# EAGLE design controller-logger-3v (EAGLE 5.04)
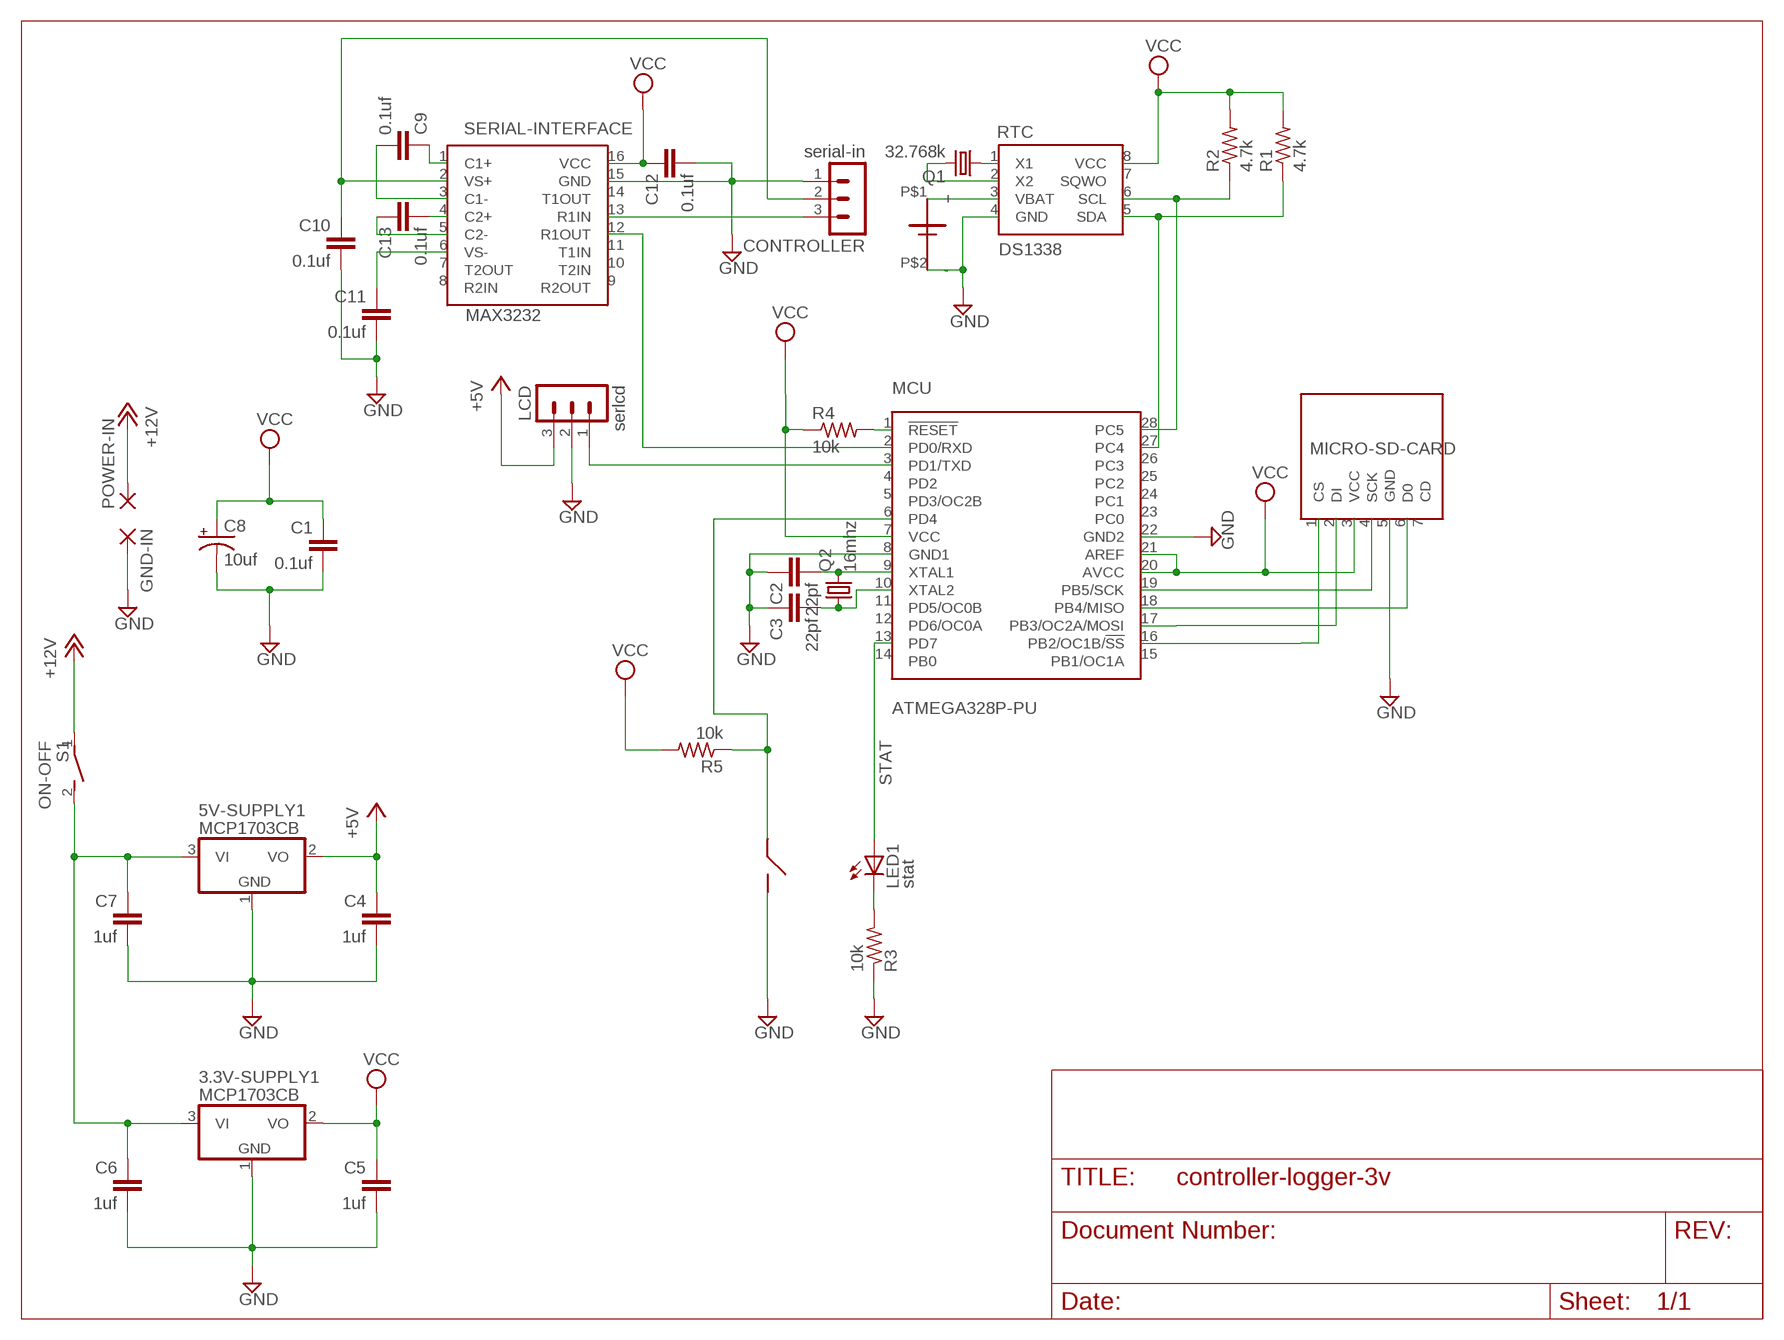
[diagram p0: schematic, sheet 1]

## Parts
3.3V-SUPPLY1  MCP1703CB  [SOT23]
5V-SUPPLY1  MCP1703CB  [SOT23]
C1  0.1uf  C2.5/2  [C2.5-2]
C2  22pf  C2.5/2  [C2.5-2]
C3  22pf  C2.5/2  [C2.5-2]
C4  1uf  C2.5/2  [C2.5-2]
C5  1uf  C2.5/2  [C2.5-2]
C6  1uf  C2.5/2  [C2.5-2]
C7  1uf  C2.5/2  [C2.5-2]
C8  10uf  CPOL-USE3.5-8  [E3,5-8]
C9  0.1uf  C2.5/2  [C2.5-2]
C10  0.1uf  C2.5/2  [C2.5-2]
C11  0.1uf  C2.5/2  [C2.5-2]
C12  0.1uf  C2.5/2  [C2.5-2]
C13  0.1uf  C2.5/2  [C2.5-2]
CONTROLLER  serial-in  MA03-1  [MA03-1]
GND-IN  1,6/0,8  [1,6/0,8]
LCD  serlcd  MA03-1  [MA03-1]
LED1  stat  LED5MM  [LED5MM]
MCU  ATMEGA328P-PU  [DIL28-3]
MICRO-SD-CARD  SFE-MICRO-SD-CARD-BREAKOUT  [SFE-MICRO-SD-CARD-BREAKOUT]
POWER-IN  1,6/0,8  [1,6/0,8]
Q1  32.768k  CRYSTALTC26V  [TC26V]
Q2  16mhz  CRYSTALTC26V  [TC26V]
R1  4.7k  R-US_0204/5  [0204/5]
R2  4.7k  R-US_0204/5  [0204/5]
R3  10k  R-US_0204/5  [0204/5]
R4  10k  R-US_0204/5  [0204/5]
R5  10k  R-US_0204/5  [0204/5]
RTC  DS1338  [8SOIC]
S1  ON-OFF  DS01E  [DS-01]
SERIAL-INTERFACE  MAX3232  MAX323216SOIC-W  [16SOIC-W]
U$1  PUSH-BUTTON-SWITCH  [2SIL]
U$3  BATTERY-COIN-16MM  [SIL2]

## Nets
+5V: 5V-SUPPLY1.2(VO) C4.1 LCD.3
+12V: POWER-IN.1(P) S1.1
GND: 3.3V-SUPPLY1.1(GND) 5V-SUPPLY1.1(GND) C1.2 C2.1 C3.1 C4.2 C5.2 C6.2 C7.2 C8.- C10.2 C11.2 C12.2 CONTROLLER.1 GND-IN.1(P) LCD.2 MCU.8(GND1) MCU.22(GND2) MICRO-SD-CARD.5(GND) R3.1 RTC.4(GND) SERIAL-INTERFACE.15(GND) U$1.COM U$3.P$2(-)
N$1: CONTROLLER.3 SERIAL-INTERFACE.13(R1IN)
N$2: Q1.1 RTC.1(X1)
N$3: Q1.2 RTC.2(X2)
N$4: LCD.1 MCU.3(PD1/TXD)
N$5: C2.2 MCU.9(XTAL1) Q2.2
N$7: LED1.K(C) R3.2
N$8: RTC.3(VBAT) U$3.P$1(+)
N$9: C3.2 MCU.10(XTAL2) Q2.1
N$10: MCU.6(PD4) R5.1 U$1.NO
N$14: 3.3V-SUPPLY1.3(VI) 5V-SUPPLY1.3(VI) C6.1 C7.1 S1.2
N$15: MCU.28(PC5) R2.1 RTC.6(SCL)
N$16: MCU.27(PC4) R1.1 RTC.5(SDA)
N$17: MCU.2(PD0/RXD) SERIAL-INTERFACE.12(R1OUT)
N$20: MCU.1(!RESET) R4.2
N$22: MCU.16(PB2/OC1B/!SS) MICRO-SD-CARD.1(CS)
N$25: MCU.18(PB4/MISO) MICRO-SD-CARD.6(D0)
N$26: C9.1 SERIAL-INTERFACE.1(C1+)
N$27: C9.2 SERIAL-INTERFACE.3(C1-)
N$28: C10.1 CONTROLLER.2 SERIAL-INTERFACE.2(VS+)
N$29: C11.1 SERIAL-INTERFACE.6(VS-)
N$30: C13.2 SERIAL-INTERFACE.4(C2+)
N$32: C13.1 SERIAL-INTERFACE.5(C2-)
N$37: MCU.19(PB5/SCK) MICRO-SD-CARD.4(SCK)
N$38: MCU.17(PB3/OC2A/MOSI) MICRO-SD-CARD.2(DI)
STAT: LED1.A MCU.13(PD7)
VCC: 3.3V-SUPPLY1.2(VO) C1.1 C5.1 C8.+ C12.1 MCU.7(VCC) MCU.20(AVCC) MCU.21(AREF) MICRO-SD-CARD.3(VCC) R1.2 R2.2 R4.1 R5.2 RTC.8(VCC) SERIAL-INTERFACE.16(VCC)
Unconnected: MCU.4(PD2) MCU.5(PD3/OC2B) MCU.11(PD5/OC0B) MCU.12(PD6/OC0A) MCU.14(PB0) MCU.15(PB1/OC1A) MCU.23(PC0) MCU.24(PC1) MCU.25(PC2) MCU.26(PC3) MICRO-SD-CARD.7(CD) RTC.7(SQWO) SERIAL-INTERFACE.7(T2OUT) SERIAL-INTERFACE.8(R2IN) SERIAL-INTERFACE.9(R2OUT) SERIAL-INTERFACE.10(T2IN) SERIAL-INTERFACE.11(T1IN) SERIAL-INTERFACE.14(T1OUT)

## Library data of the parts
3.3V-SUPPLY1 5V-SUPPLY1 = linear:MCP1703: 250 mA, 16V, Low Quiescent Current LDO Regulator Source: http://ww1.microchip.com/downloads/en/DeviceDoc/22049b.pdf
C1-C7 C9-C13 = capacitor-wima:C: CAPACITOR
C8 = resistor:CPOL-US: POLARIZED CAPACITOR, American symbol
CONTROLLER LCD = con-lstb:MA03-1: PIN HEADER
GND-IN POWER-IN = wirepad:1,6/0,8: THROUGH-HOLE PAD
LED1 = led:LED: LED
MCU = trl:ATMEGA328P-PU
MICRO-SD-CARD = trl:SFE-MICRO-SD-CARD-BREAKOUT
Q1 Q2 = crystal:CRYSTAL: CRYSTAL
R1-R5 = resistor:R-US_: RESISTOR, American symbol
RTC = trl:DS1338
S1 = switch-dil:DS01E: DIL/CODE SWITCH
SERIAL-INTERFACE = trl:MAX3232
U$1 = trl:PUSH-BUTTON-SWITCH
U$3 = trl:BATTERY-COIN-16MM

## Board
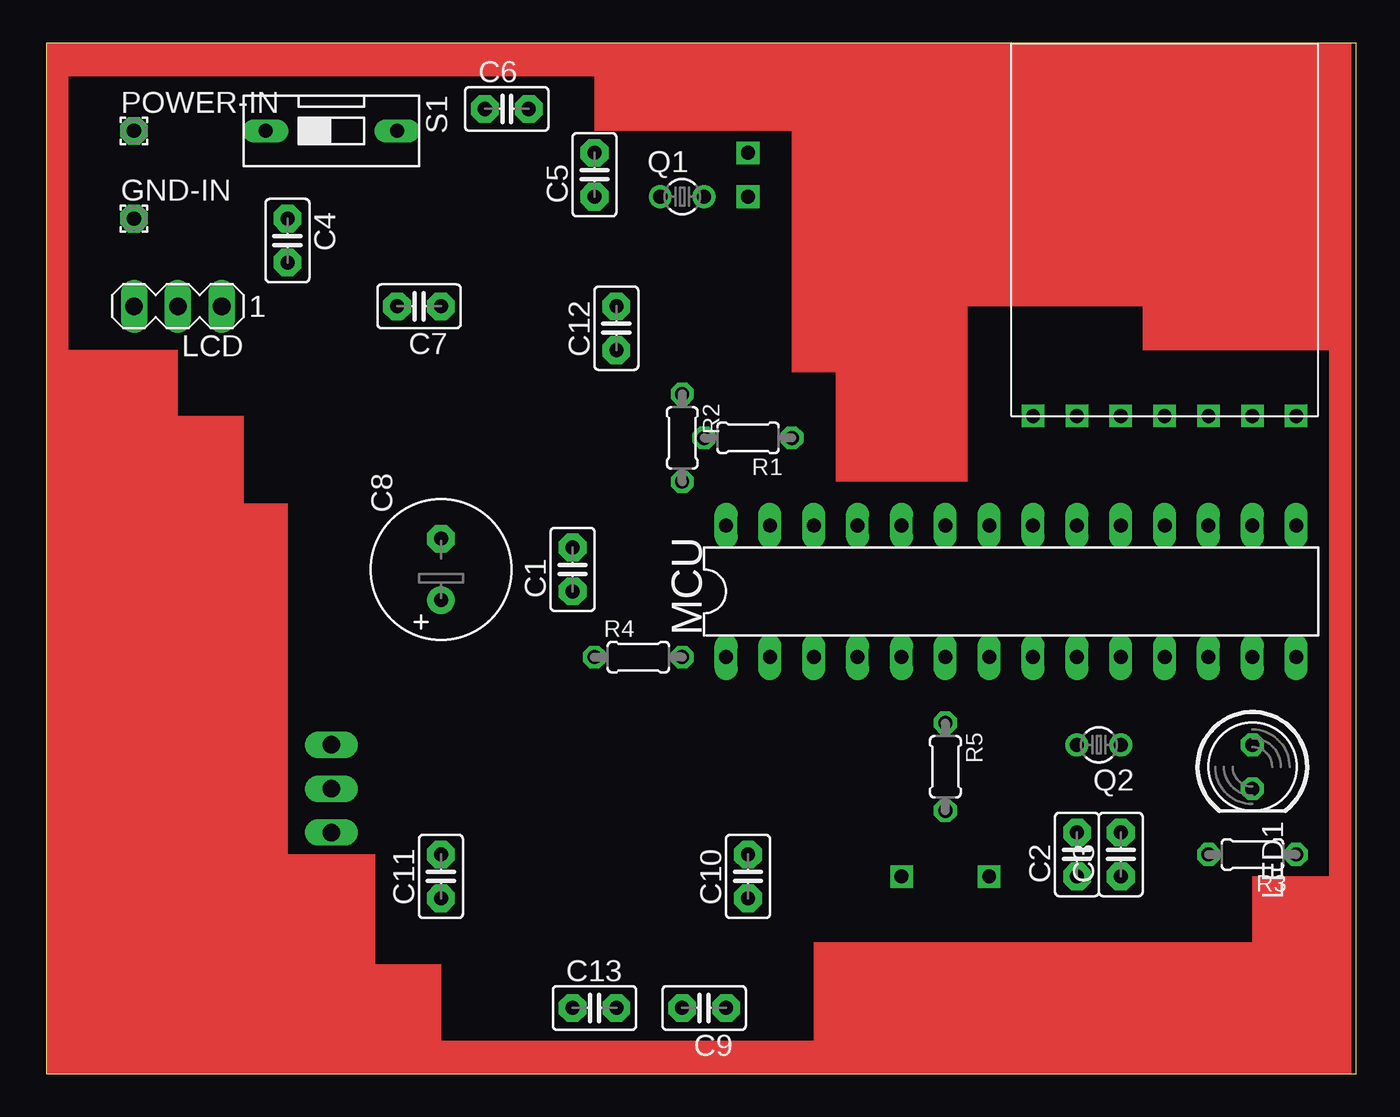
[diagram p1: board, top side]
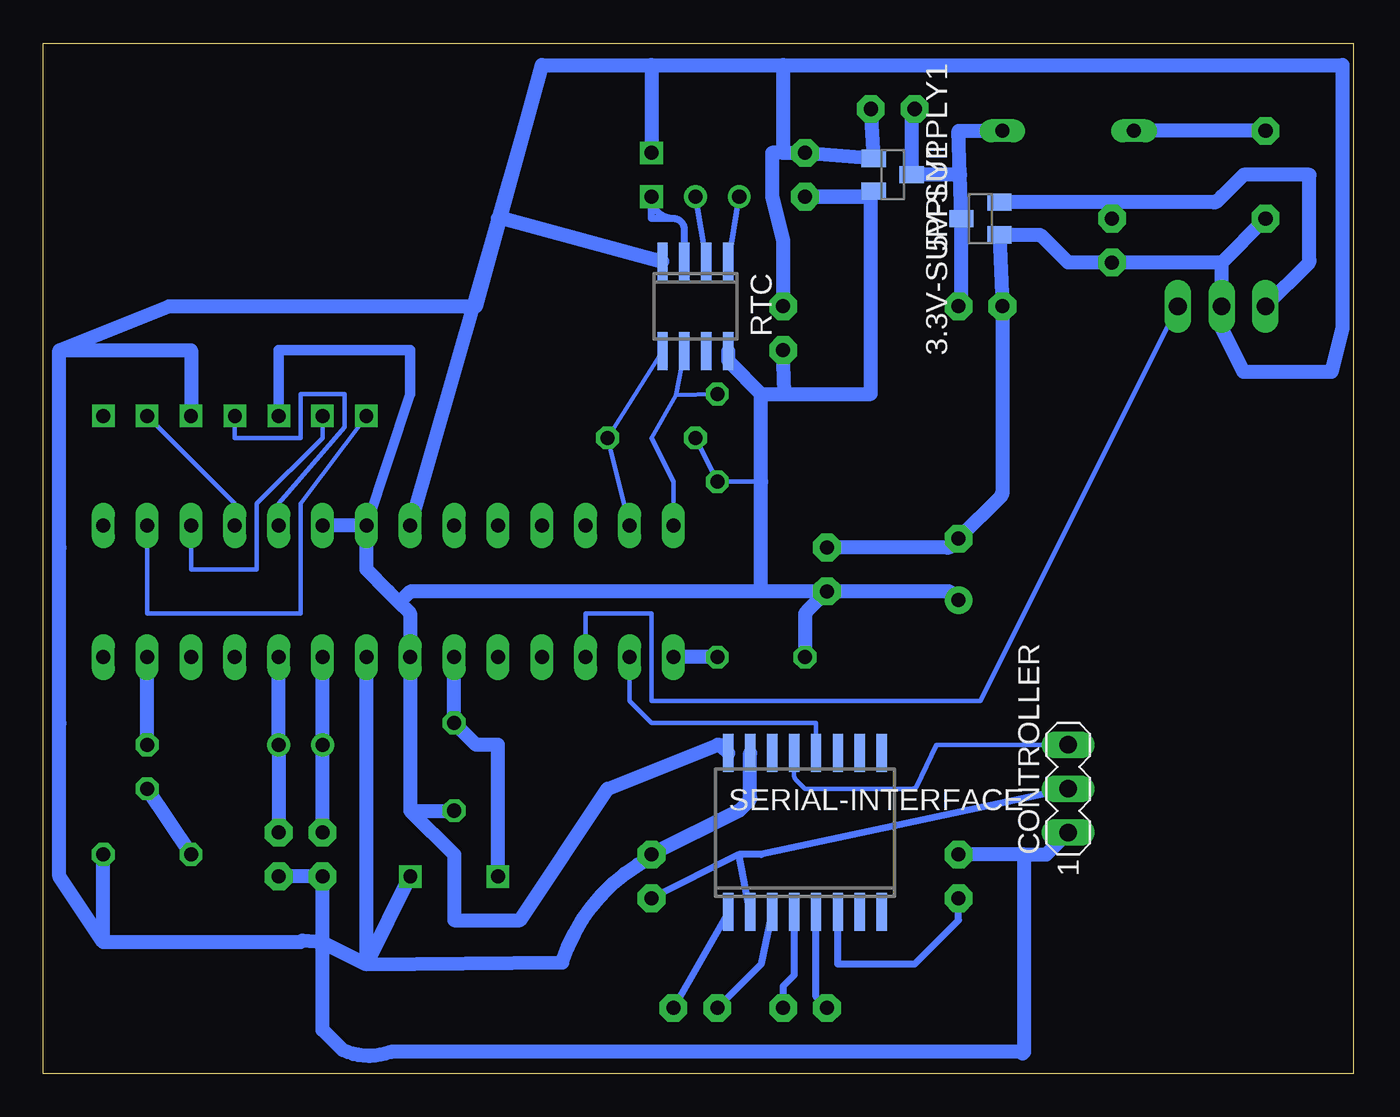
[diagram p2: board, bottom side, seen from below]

Size 75.87 x 59.68 mm. Coordinates in mm from the lower left corner, seen from the top.
Outline: 0,0 75.87,0 75.87,59.68 0,59.68 0,0
Copper layers (1*16): Top 0.035mm / dielectric 1.5mm / Bottom 0.035mm
Design rules "default": minimum track width 10mil, minimum drill 24mil, track to track 8mil, track to pad 8mil, pad to pad 8mil, via to via 8mil, smd to smd 8mil, copper to edge 40mil, drill to drill 8mil, minimum pad ring 10mil, minimum via ring 8mil, stop-mask expansion 4mil, vias tented up to drill 0mil, thermal gap 10mil

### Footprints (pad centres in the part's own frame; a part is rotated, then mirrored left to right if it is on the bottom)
SOT23 = smd 1 x 1.4: 1 -0.95,-1.1; 2 0.95,-1.1; 3 0,1.1
C2.5-2 = drill 0.813 pad 1.6 octagon: 1 -1.27,0; 2 1.27,0
E3,5-8 = drill 0.813 pad 1.6 round: + -1.778,0 | drill 0.813 pad 1.6 octagon: - 1.778,0
MA03-1 = drill 1.016 long: 1 -2.54,0; 2 0,0; 3 2.54,0
1,6/0,8 = drill 0.813 pad 1.6 octagon: 1 0,0
LED5MM = drill 0.813 octagon: A -1.27,0; K 1.27,0
DIL28-3 = drill 0.813 long: 1 -16.51,-3.81; 2 -13.97,-3.81; 3 -11.43,-3.81; 4 -8.89,-3.81; 5 -6.35,-3.81; 6 -3.81,-3.81; 7 -1.27,-3.81; 8 1.27,-3.81; 9 3.81,-3.81; 10 6.35,-3.81; 11 8.89,-3.81; 12 11.43,-3.81; 13 13.97,-3.81; 14 16.51,-3.81; 15 16.51,3.81; 16 13.97,3.81; 17 11.43,3.81; 18 8.89,3.81; 19 6.35,3.81; 20 3.81,3.81; 21 1.27,3.81; 22 -1.27,3.81; 23 -3.81,3.81; 24 -6.35,3.81; 25 -8.89,3.81; 26 -11.43,3.81; 27 -13.97,3.81; 28 -16.51,3.81
SFE-MICRO-SD-CARD-BREAKOUT = drill 0.8 square: 1 -7.62,-10.16; 2 -5.08,-10.16; 3 -2.54,-10.16; 4 0,-10.16; 5 2.54,-10.16; 6 5.08,-10.16; 7 7.62,-10.16
TC26V = drill 0.813 round: 1 -1.27,0; 2 1.27,0
0204/5 = drill 0.813 octagon: 1 -2.54,0; 2 2.54,0
8SOIC = smd 0.6 x 2.2: 1 -1.905,-2.6; 2 -0.635,-2.6; 3 0.635,-2.6; 4 1.905,-2.6; 5 1.905,2.6; 6 0.635,2.6; 7 -0.635,2.6; 8 -1.905,2.6
DS-01 = drill 0.813 long: 1 0,-3.81; 2 0,3.81
16SOIC-W = smd 0.6 x 2.2: 1 -4.445,-4.6; 2 -3.175,-4.6; 3 -1.905,-4.6; 4 -0.635,-4.6; 5 0.635,-4.6; 6 1.905,-4.6; 7 3.175,-4.6; 8 4.445,-4.6; 9 4.445,4.6; 10 3.175,4.6; 11 1.905,4.6; 12 0.635,4.6; 13 -0.635,4.6; 14 -1.905,4.6; 15 -3.175,4.6; 16 -4.445,4.6
2SIL = drill 0.8 square: COM 0,2.54; NO 0,-2.54
SIL2 = drill 0.8 square: P$1 -1.27,0; P$2 1.27,0

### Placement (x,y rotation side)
3.3V-SUPPLY1  26.67,52.07 270 bottom
5V-SUPPLY1  21.59,49.53 90 bottom
C1  30.48,29.21 90 top
C2  59.69,12.7 90 top
C3  62.23,12.7 90 top
C4  13.97,48.26 270 top
C5  31.75,52.07 90 top
C6  26.67,55.88 0 top
C7  21.59,44.45 180 top
C8  22.86,29.21 90 top
C9  38.1,3.81 180 top
C10  40.64,11.43 90 top
C11  22.86,11.43 90 top
C12  33.02,43.18 90 top
C13  31.75,3.81 0 top
CONTROLLER  16.51,16.51 90 bottom
GND-IN  5.08,49.53 0 top
LCD  7.62,44.45 180 top
LED1  69.85,17.78 270 top
MCU  55.88,27.94 0 top
MICRO-SD-CARD  64.77,48.26 0 top
POWER-IN  5.08,54.61 0 top
Q1  36.83,50.8 0 top
Q2  60.96,19.05 180 top
R1  40.64,36.83 180 top
R2  36.83,36.83 270 top
R3  69.85,12.7 180 top
R4  34.29,24.13 0 top
R5  52.07,17.78 270 top
RTC  38.1,44.45 180 bottom
S1  16.51,54.61 270 top
SERIAL-INTERFACE  31.75,13.97 0 bottom
U$1  52.07,11.43 270 top
U$3  40.64,52.07 90 top

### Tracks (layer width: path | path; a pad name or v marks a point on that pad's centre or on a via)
+5V
  Bottom 0.813: 13.97,50.48 8.07,50.48 arc-45 7.85,50.57 7.62,50.8 6.35,52.07 2.54,52.07 2.54,47.12 arc45 2.63,46.9 LCD.3 | 13.97,50.48 5V-SUPPLY1.2 | 13.97,50.48 C4.1
+12V
  Bottom 0.813: POWER-IN.1 S1.1
GND
  Bottom 0.406: 40.64,12.57 C10.2
  Bottom 0.813: C6.2 3.3V-SUPPLY1.1 C5.2 33.02,53.34 | 7.62,46.99 LCD.2 7.62,43.18 6.35,40.64 1.27,40.64 0.64,43.18 0.64,58.42 40.64,58.42 | 7.62,46.99 GND-IN.1 | 7.62,46.99 C4.2 16.51,46.99 18.01,48.49 arc-45 18.23,48.58 5V-SUPPLY1.1 C7.2 20.32,33.66 arc45 20.41,33.44 C8.- 23.27,30.57 arc45 23.5,30.48 C1.2 | C12.2 33.02,48.26 33.66,50.8 33.66,53.34 33.02,53.34 | 46.99,58.42 40.64,58.42 | 40.64,58.42 33.02,58.42 33.02,53.34 | 46.99,58.42 40.64,58.42 | 46.99,58.42 50.8,44.45 68.58,44.45 74.93,41.91 | 46.99,58.42 49.53,49.53 | 49.53,49.53 MCU.22 | RTC.4 49.38,49.59 arc-45 49.53,49.53 | 57.15,6.35 MCU.8 | 59.69,7.62 57.15,6.35 | 59.69,7.62 C2.1 C3.1 | 40.64,12.57 arc-45 45.81,6.44 57.15,6.35 | 74.93,41.91 74.93,30.48 74.93,20.32 74.93,11.43 72.39,7.62 | 72.39,7.62 61.09,7.62 arc-45 60.87,7.71 59.69,7.62 | 72.39,7.62 R3.1 | 57.15,6.35 U$1.COM | 19.05,12.7 17.78,12.7 CONTROLLER.1 | 19.05,12.7 C11.2 19.05,12.7 | 19.05,12.7 19.05,1.4 arc45 19.14,1.18 19.05,1.27 55.75,1.27 arc45 58.51,1.36 59.69,2.54 59.69,7.62 | SERIAL-INTERFACE.15 34.92,16.01 arc45 35.02,15.78 35.56,15.24 C10.2 | 40.64,58.42 U$3.P$2 | MICRO-SD-CARD.5 67.31,41.91 74.93,41.91
N$1
  Bottom 0.254: SERIAL-INTERFACE.13 32.38,17.28 arc-45 32.29,17.05 31.75,16.51 25.53,16.51 | 25.53,16.51 25.4,16.51 25.53,16.51 | 25.53,16.51 arc-45 25.31,16.6 24.13,19.05 21.59,19.05 CONTROLLER.3
N$2
  Bottom 0.305: RTC.1 Q1.1
N$3
  Bottom 0.305: RTC.2 Q1.2
N$4
  Bottom 0.254: MCU.3 44.45,26.67 40.64,26.67 40.64,21.59 30.48,21.59 25.4,21.59 21.59,21.59 LCD.1
N$5
  Bottom 0.813: C2.2 Q2.2 MCU.9
N$7
  Bottom 0.813: R3.2 LED1.K
N$8
  Bottom 0.406: RTC.3 38.73,48.9 arc-90 39.37,49.53 | 39.37,49.53 arc90 U$3.P$1 40.64,49.53 39.37,49.53
N$9
  Bottom 0.813: MCU.10 Q2.1 C3.2
N$10
  Bottom 0.813: MCU.6 R5.1 50.89,19.14 arc-45 50.67,19.05 49.53,19.05 U$1.NO
N$14
  Bottom 0.813: 22.77,52.07 5V-SUPPLY1.3 22.69,44.75 arc45 22.78,44.53 C7.1 | 22.77,52.07 22.86,54.61 S1.2 | C6.1 25.48,55.8 arc-45 25.57,55.58 3.3V-SUPPLY1.3 22.78,52.07 arc-45 22.77,52.07
N$15
  Bottom 0.254: MCU.28 39.37,34.29 40.64,36.83 39.22,39.31 | 39.22,39.31 RTC.6 | 39.22,39.31 R2.1
N$16
  Bottom 0.254: MCU.27 R1.1 RTC.5
N$17
  Bottom 0.254: SERIAL-INTERFACE.12 31.11,20.32 31.75,20.32 40.64,20.32 41.91,21.59 MCU.2
N$20
  Bottom 0.813: R4.2 MCU.1
N$22
  Bottom 0.254: MICRO-SD-CARD.1 60.96,33.02 60.96,26.67 69.85,26.67 MCU.16
N$25
  Bottom 0.254: MCU.18 64.77,33.02 MICRO-SD-CARD.6
N$26
  Bottom 0.406: SERIAL-INTERFACE.1 C9.1
N$27
  Bottom 0.406: SERIAL-INTERFACE.3 34.29,6.35 C9.2
N$28
  Bottom 0.406: 35.56,12.7 C10.1 | 35.56,12.7 34.29,12.7 CONTROLLER.2 | SERIAL-INTERFACE.2 35.56,12.7
N$29
  Bottom 0.406: SERIAL-INTERFACE.6 29.84,6.35 29.21,6.35 25.4,6.35 22.86,8.89 C11.1
N$30
  Bottom 0.406: SERIAL-INTERFACE.4 32.38,5.71 33.02,5.08 C13.2
N$32
  Bottom 0.406: C13.1 31.11,4.45 SERIAL-INTERFACE.5
N$37
  Bottom 0.254: MICRO-SD-CARD.4 64.77,36.83 60.96,36.83 60.96,39.37 58.42,39.37 58.42,38.1 58.42,37.47 62.23,33.02 MCU.19
N$38
  Bottom 0.254: MICRO-SD-CARD.2 59.69,37.47 59.69,36.83 63.5,33.02 63.5,29.21 67.31,29.21 MCU.17
STAT
  Bottom 0.813: LED1.A MCU.13
VCC
  Bottom 0.254: R1.2 R2.2 34.29,34.29
  Bottom 0.61: MCU.21 54.61,39.37 54.61,41.91 62.23,41.91 MICRO-SD-CARD.3
  Bottom 0.813: 3.3V-SUPPLY1.2 28,50.89 arc45 28.22,50.8 C5.1 27.94,50.8 27.94,39.37 34.29,39.37 | C1.1 23.5,27.94 arc45 23.27,27.85 C8.+ | R4.1 31.75,26.54 arc45 31.66,26.76 C1.1 | 55.24,27.3 54.7,26.76 arc45 54.61,26.54 MCU.7 54.61,15.24 | 55.24,27.3 55.88,27.94 57.15,29.21 MCU.21 MCU.20 | C1.1 34.29,27.94 | 34.29,27.94 54.48,27.94 arc-45 54.7,27.85 55.24,27.3 | RTC.8 36.2,41.41 arc-45 36.1,41.18 34.29,39.37 | 34.29,27.94 34.29,34.29 34.29,39.37 | 34.29,39.37 33.15,39.37 arc-45 32.93,39.46 C12.1 | 54.61,15.24 R5.2 | 54.61,15.24 52.07,12.7 52.07,8.89 48.26,8.89 43.18,16.51 36.81,19.05 arc45 36.58,18.96 SERIAL-INTERFACE.16
(copper drawn outside any net)
  shapes: Top area x21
